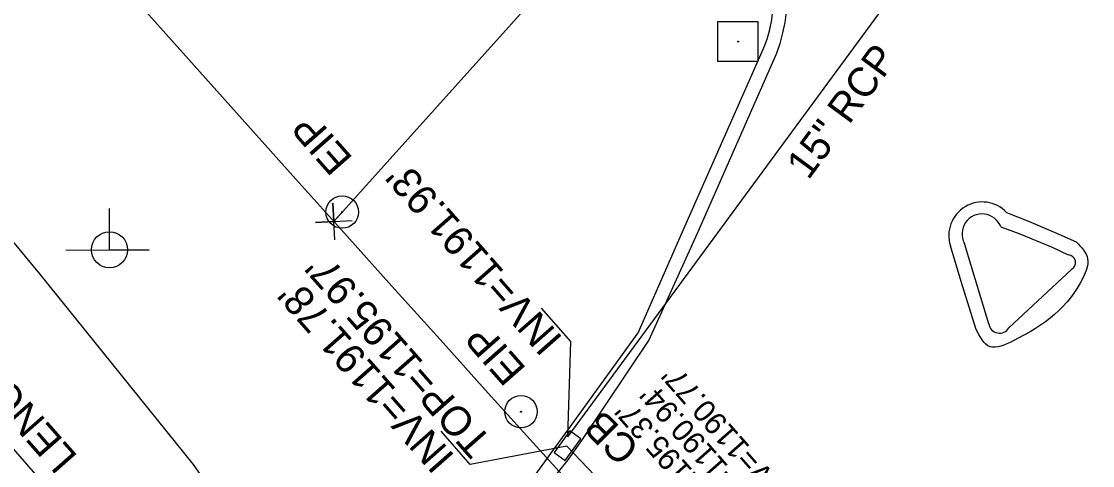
# Model space of a CAD drawing. Extents: x 1263837 to 1268319, y 770628 to 773628.
# Drawn here: x 1266621.4 to 1266766.8, y 772455.6 to 772515.9 of the extents above; entities that cross this region are included whole.
import ezdxf

# ---------------------------------------------------------------- set-up
doc = ezdxf.new("R2010")
doc.units = 0
for name, color, linetype in [('Exist Property Iron Pin Text', 7, 'Continuous'), ('Exist Structure Minor Catch Basin', 7, 'Continuous'), ('Exist Structure Minor Catch Basin Text', 7, 'Continuous'), ('Exist Structure Minor Catch Basin Top Elevation', 7, 'Continuous'), ('Exist Utilities Other Pole With Base CELL', 7, 'Continuous'), ('Exist Utilities Power Joint Use Telephone CELL', 7, 'Continuous'), ('Exist Utilities Telephone UG FO SUE LOS B', 7, 'Continuous'), ('Prop Conc 4in Sidewalk', 7, 'Continuous'), ('Prop Drainage Structure Junction Box Convert From Catch Basin Label', 7, 'Continuous'), ('Prop Drainage Structure Junction Box with Slab Lid Label', 7, 'Continuous'), ('Prop Drainage Structure Pipe RCP 60in Class III', 7, 'Continuous'), ('Prop Drainage Structure Pipe Removal Label', 7, 'Continuous'), ('Prop Guardrail', 7, 'Continuous'), ('Prop Horizontal Alignment', 7, 'Continuous'), ('Prop SS Fill Line', 7, 'Continuous'), ('Prop SS Fill Text', 7, 'Continuous'), ('Prop WCC CELL', 7, 'Continuous'), ('Scratch_Level_0', 7, 'Continuous'), ('Scratch_Level_2', 7, 'Continuous'), ('Scratch_Level_5', 7, 'Continuous'), ('Typical Terminator CELL', 7, 'Continuous')]:
    doc.layers.add(name, color=color, linetype=linetype)

# ---------------------------------------------------------------- blocks, each defined once
blk = doc.blocks.new('EXIST PROPERTY IRON PIN')
at = {"layer": 'Prop Conc 4in Sidewalk'}
for radius in [0.0441, 0.00141]:
    blk.add_circle((0, 0), radius, dxfattribs=at)
blk = doc.blocks.new('EXIST UTILITIES OTHER POLE WITH BASE')
at = {"layer": 'Exist Utilities Other Pole With Base CELL'}
blk.add_line((0, 0), (0, 0), dxfattribs=at)
blk.add_lwpolyline([(-0.0545, 0.054), (0.0535, 0.054), (0.0535, -0.054), (-0.0545, -0.054), (-0.0545, 0.054)], dxfattribs=at)
blk.add_circle((0, 0), 0.00141, dxfattribs=at)
blk = doc.blocks.new('EXIST UTILITIES POWER JOINT USE TELEPHONE')
at = {"layer": 'Exist Utilities Power Joint Use Telephone CELL'}
blk.add_line((0, 0), (0, 0), dxfattribs=at)
blk.add_lwpolyline([(-0.1188, 0), (0.108, -0.0008), (0, -0.0004), (0, 0.1125)], dxfattribs=at)
blk.add_circle((0, 0.0001), 0.049, dxfattribs=at)

msp = doc.modelspace()

# ---------------------------------------------------------------- linework, layer by layer
at = {"layer": 'Exist Structure Minor Catch Basin'}
msp.add_lwpolyline([(1266695.22, 772456.31), (1266697.36, 772459.25), (1266695.86, 772460.34), (1266693.72, 772457.4)], close=True, dxfattribs=at)
at = {"layer": 'Exist Utilities Telephone UG FO SUE LOS B'}
msp.add_lwpolyline([(1266796.47, 772289.4), (1266771.45, 772312.33), (1266750.58, 772335.58), (1266727.21, 772359.4), (1266705.16, 772382.3), (1266683.59, 772406.4), (1266666.51, 772424.57), (1266644.77, 772455.78), (1266623.87, 772481.67), (1266607.65, 772501.27), (1266583.62, 772527.54), (1266555.65, 772556.37), (1266530.83, 772582.8), (1266504.61, 772611.95), (1266480.79, 772637.46)], dxfattribs=at)
at = {"layer": 'Prop Drainage Structure Pipe RCP 60in Class III'}
msp.add_line((1266663.79, 772488.79), (1266663.79, 772488.79), dxfattribs=at)
msp.add_lwpolyline([(1266663.93, 772486.3), (1266663.66, 772491.29), (1266663.79, 772488.79), (1266661.3, 772488.66), (1266666.29, 772488.93)], dxfattribs=at)
at = {"layer": 'Prop Guardrail'}
for p, q in [((1266663.79, 772488.79), (1266836.9, 772681.55)), ((1266663.98, 772489), (1266664.94, 772490.06))]:
    msp.add_line(p, q, dxfattribs=at)
at = {"layer": 'Prop Horizontal Alignment'}
msp.add_arc((1275094.23, 780056.99), 11329.16, 216.983333, 223.309327, dxfattribs=at)
at = {"layer": 'Prop SS Fill Line'}
for p, q in [((1266750.89, 772480.99), (1266749.42, 772485.81)), ((1266750.89, 772480.99), (1266749.42, 772485.81)), ((1266750.89, 772480.99), (1266749.42, 772485.81)), ((1266750.89, 772480.99), (1266749.42, 772485.81)), ((1266761.33, 772485.3), (1266763.53, 772484.23)), ((1266761.33, 772485.3), (1266763.53, 772484.23)), ((1266761.33, 772485.3), (1266763.53, 772484.23)), ((1266761.33, 772485.3), (1266763.53, 772484.23)), ((1266763.96, 772482.28), (1266755.47, 772474.33)), ((1266763.96, 772482.28), (1266755.47, 772474.33)), ((1266763.96, 772482.28), (1266755.47, 772474.33)), ((1266763.96, 772482.28), (1266755.47, 772474.33)), ((1266752.73, 772474.88), (1266750.89, 772480.99)), ((1266752.73, 772474.88), (1266750.89, 772480.99)), ((1266752.73, 772474.88), (1266750.89, 772480.99)), ((1266752.73, 772474.88), (1266750.89, 772480.99))]:
    msp.add_line(p, q, dxfattribs=at)
for points in [[(1266682.11, 772441.94), (1266688.07, 772450.07), (1266693.64, 772457.75), (1266695.58, 772460.43), (1266705.13, 772473.67), (1266711.48, 772488.08), (1266722.16, 772512.27)], [(1266682.11, 772441.94), (1266688.07, 772450.07), (1266693.64, 772457.75), (1266695.58, 772460.43), (1266705.13, 772473.67), (1266711.48, 772488.08), (1266722.16, 772512.27)], [(1266682.11, 772441.94), (1266688.07, 772450.07), (1266693.64, 772457.75), (1266695.58, 772460.43), (1266705.13, 772473.67), (1266711.48, 772488.08), (1266722.16, 772512.27)], [(1266682.11, 772441.94), (1266688.07, 772450.07), (1266693.64, 772457.75), (1266695.58, 772460.43), (1266705.13, 772473.67), (1266711.48, 772488.08), (1266722.16, 772512.27)], [(1266754.38, 772488.04), (1266756.96, 772487.12), (1266761.33, 772485.3)], [(1266754.38, 772488.04), (1266756.96, 772487.12), (1266761.33, 772485.3)], [(1266754.38, 772488.04), (1266756.96, 772487.12), (1266761.33, 772485.3)], [(1266754.38, 772488.04), (1266756.96, 772487.12), (1266761.33, 772485.3)]]:
    msp.add_lwpolyline(points, dxfattribs=at)
for centre, major_axis, ratio, start_param, end_param in [((1266705.44, 772519.07), (17.7, -3.57), 0.999643, 6.09564, 7.283429), ((1266705.44, 772519.07), (17.7, -3.57), 0.999643, 6.09564, 7.283429), ((1266705.44, 772519.07), (17.7, -3.57), 0.999643, 6.09564, 7.283429), ((1266705.44, 772519.07), (17.7, -3.57), 0.999643, 6.09564, 7.283429), ((1266751.82, 772487.09), (1.96, -1.89), 0.999898, 1.123499, 4.39885), ((1266751.82, 772487.09), (1.96, -1.89), 0.999898, 1.123499, 4.39885), ((1266751.82, 772487.09), (1.96, -1.89), 0.999898, 1.123499, 4.39885), ((1266751.82, 772487.09), (1.96, -1.89), 0.999898, 1.123499, 4.39885), ((1266763.48, 772483.2), (0.07, 1.03), 0.999315, 3.691497, 6.309196), ((1266763.48, 772483.2), (0.07, 1.03), 0.999315, 3.691497, 6.309196), ((1266763.48, 772483.2), (0.07, 1.03), 0.999315, 3.691497, 6.309196), ((1266763.48, 772483.2), (0.07, 1.03), 0.999315, 3.691497, 6.309196), ((1266754.2, 772475.09), (1.43, -0.38), 0.999089, 3.538624, 6.003487), ((1266754.2, 772475.09), (1.43, -0.38), 0.999089, 3.538624, 6.003487), ((1266754.2, 772475.09), (1.43, -0.38), 0.999089, 3.538624, 6.003487), ((1266754.2, 772475.09), (1.43, -0.38), 0.999089, 3.538624, 6.003487)]:
    msp.add_ellipse(centre, major_axis=major_axis, ratio=ratio, start_param=start_param, end_param=end_param, dxfattribs=at)
at = {"layer": 'Prop SS Fill Text'}
msp.add_line((1266762.26, 772487.04), (1266764.59, 772486.04), dxfattribs=at)
for points in [[(1266684.18, 772440.48), (1266689.51, 772448.82), (1266695.61, 772456.43), (1266697.55, 772459.16), (1266706.57, 772472.61), (1266713.19, 772487.18), (1266723.89, 772511.55)], [(1266755.16, 772490.02), (1266758.14, 772488.84), (1266762.26, 772487.04)], [(1266750.96, 772474.23), (1266748.98, 772480.61), (1266747.52, 772485.47)]]:
    msp.add_lwpolyline(points, dxfattribs=at)
msp.add_arc((1266751.86, 772486.87), 4.56, 43.6187, 197.9461, dxfattribs=at)
msp.add_ellipse((1266705.04, 772519.09), major_axis=(14.65, -14.06), ratio=0.999291, start_param=0.384717, end_param=1.534625, dxfattribs=at)
msp.add_spline([(1266764.59, 772486.04), (1266766.15, 772483.7), (1266765.53, 772481.17), (1266756.03, 772472.56), (1266752.92, 772471.77), (1266750.96, 772474.23)], degree=3, dxfattribs=at)
at = {"layer": 'Prop WCC CELL'}
for p, q in [((1266695.56, 772459.55), (1266794.55, 772594.23)), ((1266717.98, 772434.56), (1266695.46, 772458.29))]:
    msp.add_line(p, q, dxfattribs=at)
at = {"layer": 'Scratch_Level_2'}
msp.add_arc((1275094.23, 780056.99), 11459.16, 216.983333, 225.433333, dxfattribs=at)
at = {"layer": 'Scratch_Level_5'}
msp.add_line((1266484.76, 772611.98), (1266772.72, 772284.51), dxfattribs=at)
at = {"layer": 'Typical Terminator CELL'}
for points in [[(1266695.56, 772459.55), (1266695.98, 772472.49), (1266692.01, 772477)], [(1266695.46, 772458.29), (1266682.32, 772455.8), (1266678.36, 772460.3)]]:
    msp.add_lwpolyline(points, dxfattribs=at)

# ---------------------------------------------------------------- block references
at = {"layer": 'Exist Utilities Other Pole With Base CELL', "xscale": 50, "yscale": 50}
msp.add_blockref('EXIST UTILITIES OTHER POLE WITH BASE', (1266718.69, 772513.22), dxfattribs=at)
at = {"layer": 'Exist Utilities Power Joint Use Telephone CELL', "xscale": 50, "yscale": 50}
msp.add_blockref('EXIST UTILITIES POWER JOINT USE TELEPHONE', (1266633.35, 772484.94), dxfattribs=at)
at = {"layer": 'Prop Conc 4in Sidewalk', "xscale": 50, "yscale": 50}
for p in [(1266664.94, 772490.06), (1266689.22, 772462.95)]:
    msp.add_blockref('EXIST PROPERTY IRON PIN', p, dxfattribs=at)

# ---------------------------------------------------------------- texts
at = {"layer": 'Exist Property Iron Pin Text'}
for p in [(1266666.5, 772497.36), (1266690.05, 772468.79)]:
    msp.add_text('EIP', height=4, rotation=131.3556, dxfattribs=at).set_placement(p)
at = {"layer": 'Exist Structure Minor Catch Basin Text'}
msp.add_text('CB', height=4, rotation=135.4239, dxfattribs=at).set_placement((1266705.52, 772458.19))
at = {"layer": 'Exist Structure Minor Catch Basin Top Elevation'}
for s, height, p in [("TOP=1195.97'", 4, (1266685.44, 772459.01)), ("TOP=1195.37'", 3, (1266721.09, 772445.38))]:
    msp.add_text(s, height=height, rotation=131.3556, dxfattribs=at).set_placement(p)
at = {"layer": 'Prop Drainage Structure Junction Box Convert From Catch Basin Label'}
msp.add_text("INV=1190.77'", height=3, rotation=131.3556, dxfattribs=at).set_placement((1266726.38, 772451.4))
at = {"layer": 'Prop Drainage Structure Junction Box with Slab Lid Label'}
for s, height, p in [("INV=1191.93'", 4, (1266695.02, 772472.89)), ("INV=1191.78'", 4, (1266680.35, 772456.89)), ("INV=1190.94'", 3, (1266723.44, 772448.78))]:
    msp.add_text(s, height=height, rotation=131.3556, dxfattribs=at).set_placement(p)
at = {"layer": 'Prop Drainage Structure Pipe Removal Label'}
msp.add_text('15" RCP', height=4, rotation=53.6862, dxfattribs=at).set_placement((1266728.23, 772494.3))
at = {"layer": 'Scratch_Level_0'}
msp.add_text('8" VCP CITY OF LENOIR', height=4, rotation=131.3273, dxfattribs=at).set_placement((1266656.5, 772425.76))

doc.saveas('drawing.dxf')
